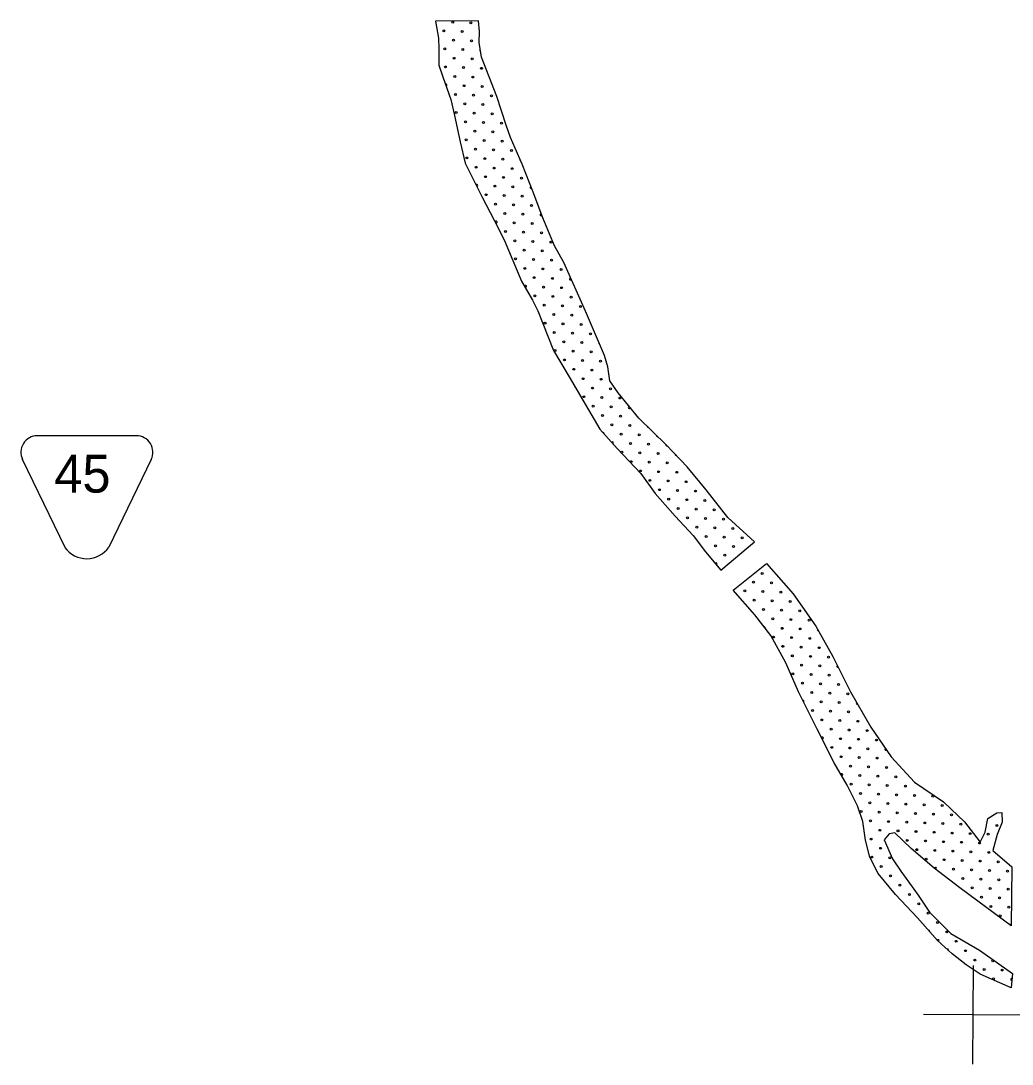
# Model space of a CAD drawing. Extents: x 1612280 to 1883141, y 560852 to 780851.
# Drawn here: x 1761295 to 1772365, y 697806 to 709453 of the extents above; entities that cross this region are included whole.
import ezdxf

# ---------------------------------------------------------------- set-up
doc = ezdxf.new("R2010")
doc.units = 0
for name, color, linetype in [('DESIGN - ROW - Easement Linework and Patterning', 7, 'Continuous'), ('DESIGN - SCRATCH - User 1', 7, 'Continuous'), ('DESIGN - TRAFFIC CONTROL PERMANENT - Pavement Marking Text', 7, 'Continuous'), ('SURVEY - DRAINAGE - Bridge Hydraulic Data - Points - Locators', 7, 'Continuous')]:
    doc.layers.add(name, color=color, linetype=linetype)

msp = doc.modelspace()

# ---------------------------------------------------------------- linework, layer by layer
at = {"layer": 'DESIGN - ROW - Easement Linework and Patterning'}
for p, q in [((1762584, 704821), (1761480, 704821)), ((1762584, 704821), (1761480, 704821)), ((1761788, 703575), (1761313, 704555)), ((1761788, 703575), (1761313, 704555)), ((1762750, 704555), (1762277, 703578)), ((1762750, 704555), (1762277, 703578))]:
    msp.add_line(p, q, dxfattribs=at)
for centre, radius, start, end in [((1761480, 704636), 185, 90.0012, 205.8236), ((1761480, 704636), 185, 90.0012, 205.8236), ((1762584, 704636), 185, 334.1799, 90.0012), ((1762584, 704636), 185, 334.1799, 90.0012), ((1762031, 703746), 298, 215.1371, 325.5451), ((1762031, 703746), 298, 215.1371, 325.5451)]:
    msp.add_arc(centre, radius, start, end, dxfattribs=at)
at = {"layer": 'DESIGN - SCRATCH - User 1'}
for points in [[(1767357, 706757), (1767255, 706943), (1767122, 707255), (1767014, 707541), (1766892, 707853), (1766764, 708149), (1766713, 708287), (1766611, 708609), (1766437, 709049), (1766412, 709213), (1766417, 709335), (1766406, 709453), (1765926, 709448), (1765957, 709259), (1765962, 709141), (1765962, 708957), (1766008, 708829), (1766095, 708574), (1766136, 708395), (1766202, 708103), (1766258, 707863), (1766340, 707699), (1766447, 707485), (1766580, 707229), (1766692, 707007)], [(1767357, 706757), (1767255, 706943), (1767122, 707255), (1767014, 707541), (1766892, 707853), (1766764, 708149), (1766713, 708287), (1766611, 708609), (1766437, 709049), (1766412, 709213), (1766417, 709335), (1766406, 709453), (1765926, 709448), (1765957, 709259), (1765962, 709141), (1765962, 708957), (1766008, 708829), (1766095, 708574), (1766136, 708395), (1766202, 708103), (1766258, 707863), (1766340, 707699), (1766447, 707485), (1766580, 707229), (1766692, 707007)], [(1766692, 707007), (1766885, 706546), (1767010, 706336), (1767067, 706217), (1767243, 705774), (1767419, 705478), (1767635, 705109), (1767760, 704893), (1767953, 704677), (1768220, 704399), (1768379, 704177), (1768600, 703922), (1768804, 703706), (1768941, 703524), (1769111, 703319)], [(1766692, 707007), (1766885, 706546), (1767010, 706336), (1767067, 706217), (1767243, 705774), (1767419, 705478), (1767635, 705109), (1767760, 704893), (1767953, 704677), (1768220, 704399), (1768379, 704177), (1768600, 703922), (1768804, 703706), (1768941, 703524), (1769111, 703319)], [(1769111, 703319), (1769486, 703638), (1769190, 703910), (1768946, 704217), (1768736, 704473), (1768503, 704717), (1768197, 705018), (1767964, 705302), (1767873, 705433), (1767850, 705592), (1767811, 705717), (1767601, 706211), (1767357, 706757)], [(1769111, 703319), (1769486, 703638), (1769190, 703910), (1768946, 704217), (1768736, 704473), (1768503, 704717), (1768197, 705018), (1767964, 705302), (1767873, 705433), (1767850, 705592), (1767811, 705717), (1767601, 706211), (1767357, 706757)], [(1769251, 703096), (1769621, 703396), (1769920, 703057), (1770172, 702694), (1770361, 702356), (1770558, 701962), (1770786, 701568), (1771015, 701237), (1771274, 700953), (1771597, 700733), (1771684, 700654), (1771833, 700512), (1772007, 700284)], [(1769251, 703096), (1769621, 703396), (1769920, 703057), (1770172, 702694), (1770361, 702356), (1770558, 701962), (1770786, 701568), (1771015, 701237), (1771274, 700953), (1771597, 700733), (1771684, 700654), (1771833, 700512), (1772007, 700284)], [(1770697, 700514), (1770638, 700689), (1770522, 700919), (1770378, 701168), (1770186, 701545), (1769979, 701963), (1769836, 702287), (1769670, 702592), (1769490, 702822), (1769251, 703096)], [(1770697, 700514), (1770638, 700689), (1770522, 700919), (1770378, 701168), (1770186, 701545), (1769979, 701963), (1769836, 702287), (1769670, 702592), (1769490, 702822), (1769251, 703096)], [(1772007, 700284), (1772064, 700397), (1772092, 700547), (1772195, 700611), (1772249, 700615), (1772252, 700508), (1772199, 700369), (1772149, 700191), (1772363, 700009), (1772352, 699350), (1771782, 699774), (1771494, 699995), (1771238, 700212), (1771056, 700387), (1770992, 700376)], [(1772007, 700284), (1772064, 700397), (1772092, 700547), (1772195, 700611), (1772249, 700615), (1772252, 700508), (1772199, 700369), (1772149, 700191), (1772363, 700009), (1772352, 699350), (1771782, 699774), (1771494, 699995), (1771238, 700212), (1771056, 700387), (1770992, 700376)], [(1770992, 700376), (1770934, 700309), (1771029, 700097), (1771122, 699959), (1771316, 699692), (1771443, 699502), (1771680, 699264), (1772001, 699079), (1772368, 698819), (1772353, 698657), (1772009, 698810), (1771850, 698914), (1771694, 699036), (1771530, 699186), (1771307, 699438), (1771061, 699698), (1770868, 699935), (1770775, 700115), (1770726, 700306), (1770697, 700514)], [(1770992, 700376), (1770934, 700309), (1771029, 700097), (1771122, 699959), (1771316, 699692), (1771443, 699502), (1771680, 699264), (1772001, 699079), (1772368, 698819), (1772353, 698657), (1772009, 698810), (1771850, 698914), (1771694, 699036), (1771530, 699186), (1771307, 699438), (1771061, 699698), (1770868, 699935), (1770775, 700115), (1770726, 700306), (1770697, 700514)]]:
    msp.add_lwpolyline(points, dxfattribs=at)
for centre in [(1767260, 705772), (1767260, 705772), (1767461, 705765), (1767461, 705765), (1767364, 705667), (1767364, 705667), (1767566, 705660), (1767566, 705660), (1770769, 700924), (1770769, 700924), (1770873, 700820), (1770873, 700820), (1770978, 700715), (1770978, 700715), (1771082, 700610), (1771082, 700610)]:
    msp.add_circle(centre, 10.6, dxfattribs=at)
at = {"layer": 'DESIGN - TRAFFIC CONTROL PERMANENT - Pavement Marking Text'}
for centre in [(1766117, 709438), (1766117, 709438), (1766319, 709431), (1766319, 709431), (1766020, 709341), (1766020, 709341), (1766222, 709334), (1766222, 709334), (1766125, 709237), (1766125, 709237), (1766326, 709229), (1766326, 709229), (1766028, 709140), (1766028, 709140), (1766229, 709132), (1766229, 709132), (1766132, 709035), (1766132, 709035), (1766334, 709028), (1766334, 709028), (1766035, 708938), (1766035, 708938), (1766237, 708931), (1766237, 708931), (1766438, 708923), (1766438, 708923), (1766140, 708833), (1766140, 708833), (1766244, 708729), (1766244, 708729), (1766341, 708826), (1766341, 708826), (1766147, 708632), (1766147, 708632), (1766349, 708624), (1766349, 708624), (1766446, 708721), (1766446, 708721), (1766550, 708617), (1766550, 708617), (1766252, 708527), (1766252, 708527), (1766453, 708520), (1766453, 708520), (1766155, 708430), (1766155, 708430), (1766356, 708423), (1766356, 708423), (1766558, 708415), (1766558, 708415), (1766259, 708326), (1766259, 708326), (1766461, 708318), (1766461, 708318), (1766662, 708311), (1766662, 708311), (1766364, 708221), (1766364, 708221), (1766565, 708214), (1766565, 708214), (1766267, 708124), (1766267, 708124), (1766468, 708117), (1766468, 708117), (1766670, 708109), (1766670, 708109), (1766274, 707922), (1766274, 707922), (1766371, 708020), (1766371, 708020), (1766476, 707915), (1766476, 707915), (1766573, 708012), (1766573, 708012), (1766774, 708005), (1766774, 708005), (1766379, 707818), (1766379, 707818), (1766580, 707810), (1766580, 707810), (1766677, 707908), (1766677, 707908), (1766782, 707803), (1766782, 707803), (1766483, 707713), (1766483, 707713), (1766685, 707706), (1766685, 707706), (1766886, 707698), (1766886, 707698), (1766588, 707609), (1766588, 707609), (1766789, 707601), (1766789, 707601), (1766491, 707512), (1766491, 707512), (1766692, 707504), (1766692, 707504), (1766894, 707497), (1766894, 707497), (1766595, 707407), (1766595, 707407), (1766797, 707400), (1766797, 707400), (1766998, 707392), (1766998, 707392), (1766700, 707303), (1766700, 707303), (1766901, 707295), (1766901, 707295), (1766707, 707101), (1766707, 707101), (1766804, 707198), (1766804, 707198), (1767006, 707191), (1767006, 707191), (1766812, 706997), (1766812, 706997), (1766909, 707094), (1766909, 707094), (1767013, 706989), (1767013, 706989), (1767110, 707086), (1767110, 707086), (1767215, 706982), (1767215, 706982), (1766916, 706892), (1766916, 706892), (1767118, 706885), (1767118, 706885), (1766819, 706795), (1766819, 706795), (1767021, 706788), (1767021, 706788), (1767222, 706780), (1767222, 706780), (1766924, 706690), (1766924, 706690), (1767125, 706683), (1767125, 706683), (1767327, 706676), (1767327, 706676), (1767028, 706586), (1767028, 706586), (1767230, 706578), (1767230, 706578), (1767133, 706481), (1767133, 706481), (1767334, 706474), (1767334, 706474), (1767036, 706384), (1767036, 706384), (1767237, 706377), (1767237, 706377), (1767439, 706369), (1767439, 706369), (1767140, 706280), (1767140, 706280), (1767245, 706175), (1767245, 706175), (1767342, 706272), (1767342, 706272), (1767446, 706168), (1767446, 706168), (1767543, 706265), (1767543, 706265), (1767148, 706078), (1767148, 706078), (1767349, 706071), (1767349, 706071), (1767551, 706063), (1767551, 706063), (1767252, 705974), (1767252, 705974), (1767454, 705966), (1767454, 705966), (1767655, 705959), (1767655, 705959), (1767357, 705869), (1767357, 705869), (1767558, 705862), (1767558, 705862), (1767663, 705757), (1767663, 705757), (1767767, 705653), (1767767, 705653), (1767469, 705563), (1767469, 705563), (1767670, 705555), (1767670, 705555), (1767573, 705458), (1767573, 705458), (1767678, 705354), (1767678, 705354), (1767775, 705451), (1767775, 705451), (1767581, 705257), (1767581, 705257), (1767782, 705249), (1767782, 705249), (1767879, 705346), (1767879, 705346), (1767984, 705242), (1767984, 705242), (1767685, 705152), (1767685, 705152), (1767887, 705145), (1767887, 705145), (1767790, 705048), (1767790, 705048), (1767991, 705040), (1767991, 705040), (1767894, 704943), (1767894, 704943), (1768096, 704936), (1768096, 704936), (1767999, 704839), (1767999, 704839), (1768201, 704831), (1768201, 704831), (1768103, 704734), (1768103, 704734), (1768305, 704727), (1768305, 704727), (1768006, 704637), (1768006, 704637), (1768208, 704630), (1768208, 704630), (1768410, 704622), (1768410, 704622), (1768111, 704532), (1768111, 704532), (1768215, 704428), (1768215, 704428), (1768313, 704525), (1768313, 704525), (1768417, 704420), (1768417, 704420), (1768514, 704518), (1768514, 704518), (1768320, 704323), (1768320, 704323), (1768522, 704316), (1768522, 704316), (1768619, 704413), (1768619, 704413), (1768723, 704308), (1768723, 704308), (1768425, 704219), (1768425, 704219), (1768626, 704211), (1768626, 704211), (1768828, 704204), (1768828, 704204), (1768529, 704114), (1768529, 704114), (1768731, 704107), (1768731, 704107), (1768932, 704099), (1768932, 704099), (1768634, 704010), (1768634, 704010), (1768835, 704002), (1768835, 704002), (1769037, 703995), (1769037, 703995), (1768738, 703905), (1768738, 703905), (1768940, 703898), (1768940, 703898), (1769141, 703890), (1769141, 703890), (1768843, 703801), (1768843, 703801), (1769044, 703793), (1769044, 703793), (1769246, 703786), (1769246, 703786), (1768947, 703696), (1768947, 703696), (1769149, 703689), (1769149, 703689), (1769350, 703681), (1769350, 703681), (1769052, 703592), (1769052, 703592), (1769156, 703487), (1769156, 703487), (1769253, 703584), (1769253, 703584), (1769574, 703284), (1769574, 703284), (1769477, 703187), (1769477, 703187), (1769678, 703179), (1769678, 703179), (1769380, 703090), (1769380, 703090), (1769581, 703082), (1769581, 703082), (1769783, 703075), (1769783, 703075), (1769484, 702985), (1769484, 702985), (1769686, 702978), (1769686, 702978), (1769887, 702970), (1769887, 702970), (1769589, 702880), (1769589, 702880), (1769790, 702873), (1769790, 702873), (1769992, 702866), (1769992, 702866), (1769693, 702776), (1769693, 702776), (1769798, 702671), (1769798, 702671), (1769895, 702768), (1769895, 702768), (1770097, 702761), (1770097, 702761), (1769701, 702574), (1769701, 702574), (1769902, 702567), (1769902, 702567), (1769999, 702664), (1769999, 702664), (1770104, 702559), (1770104, 702559), (1769805, 702470), (1769805, 702470), (1770007, 702462), (1770007, 702462), (1770209, 702455), (1770209, 702455), (1769910, 702365), (1769910, 702365), (1770112, 702358), (1770112, 702358), (1770313, 702350), (1770313, 702350), (1770014, 702261), (1770014, 702261), (1770216, 702253), (1770216, 702253), (1769917, 702164), (1769917, 702164), (1770119, 702156), (1770119, 702156), (1770321, 702149), (1770321, 702149), (1770022, 702059), (1770022, 702059), (1770224, 702052), (1770224, 702052), (1770425, 702044), (1770425, 702044), (1770126, 701955), (1770126, 701955), (1770328, 701947), (1770328, 701947), (1770530, 701940), (1770530, 701940), (1770134, 701753), (1770134, 701753), (1770231, 701850), (1770231, 701850), (1770336, 701745), (1770336, 701745), (1770433, 701843), (1770433, 701843), (1770537, 701738), (1770537, 701738), (1770238, 701648), (1770238, 701648), (1770440, 701641), (1770440, 701641), (1770642, 701633), (1770642, 701633), (1770343, 701544), (1770343, 701544), (1770545, 701536), (1770545, 701536), (1770746, 701529), (1770746, 701529), (1770448, 701439), (1770448, 701439), (1770649, 701432), (1770649, 701432), (1770851, 701424), (1770851, 701424), (1770350, 701342), (1770350, 701342), (1770552, 701335), (1770552, 701335), (1770754, 701327), (1770754, 701327), (1770455, 701238), (1770455, 701238), (1770657, 701230), (1770657, 701230), (1770858, 701223), (1770858, 701223), (1770560, 701133), (1770560, 701133), (1770761, 701126), (1770761, 701126), (1770963, 701118), (1770963, 701118), (1770567, 700932), (1770567, 700932), (1770664, 701029), (1770664, 701029), (1770866, 701021), (1770866, 701021), (1771067, 701014), (1771067, 701014), (1770672, 700827), (1770672, 700827), (1770970, 700917), (1770970, 700917), (1771075, 700812), (1771075, 700812), (1771172, 700909), (1771172, 700909), (1770776, 700722), (1770776, 700722), (1771179, 700708), (1771179, 700708), (1771276, 700805), (1771276, 700805), (1771381, 700700), (1771381, 700700), (1771478, 700797), (1771478, 700797), (1771583, 700693), (1771583, 700693), (1770679, 700625), (1770679, 700625), (1770881, 700618), (1770881, 700618), (1771284, 700603), (1771284, 700603), (1771485, 700596), (1771485, 700596), (1771687, 700588), (1771687, 700588), (1770784, 700521), (1770784, 700521), (1770985, 700513), (1770985, 700513), (1771187, 700506), (1771187, 700506), (1771388, 700498), (1771388, 700498), (1771590, 700491), (1771590, 700491), (1771792, 700484), (1771792, 700484), (1772195, 700469), (1772195, 700469), (1770888, 700416), (1770888, 700416), (1771090, 700409), (1771090, 700409), (1771291, 700401), (1771291, 700401), (1771493, 700394), (1771493, 700394), (1771695, 700386), (1771695, 700386), (1771896, 700379), (1771896, 700379), (1772098, 700372), (1772098, 700372), (1770791, 700319), (1770791, 700319), (1771194, 700304), (1771194, 700304), (1771396, 700297), (1771396, 700297), (1771597, 700289), (1771597, 700289), (1771799, 700282), (1771799, 700282), (1772001, 700274), (1772001, 700274), (1770798, 700118), (1770798, 700118), (1770896, 700215), (1770896, 700215), (1771000, 700110), (1771000, 700110), (1771299, 700200), (1771299, 700200), (1771500, 700192), (1771500, 700192), (1771702, 700185), (1771702, 700185), (1771904, 700177), (1771904, 700177), (1772105, 700170), (1772105, 700170), (1770903, 700013), (1770903, 700013), (1771403, 700095), (1771403, 700095), (1771605, 700088), (1771605, 700088), (1771807, 700080), (1771807, 700080), (1772008, 700073), (1772008, 700073), (1772210, 700065), (1772210, 700065), (1771008, 699909), (1771008, 699909), (1771709, 699983), (1771709, 699983), (1771814, 699879), (1771814, 699879), (1771911, 699976), (1771911, 699976), (1772113, 699968), (1772113, 699968), (1772314, 699961), (1772314, 699961), (1771112, 699804), (1771112, 699804), (1771919, 699774), (1771919, 699774), (1772016, 699871), (1772016, 699871), (1772120, 699767), (1772120, 699767), (1772217, 699864), (1772217, 699864), (1772322, 699759), (1772322, 699759), (1771217, 699700), (1771217, 699700), (1772023, 699670), (1772023, 699670), (1772225, 699662), (1772225, 699662), (1771321, 699595), (1771321, 699595), (1772128, 699565), (1772128, 699565), (1772329, 699558), (1772329, 699558), (1771426, 699490), (1771426, 699490), (1772232, 699461), (1772232, 699461), (1771530, 699386), (1771530, 699386), (1771635, 699281), (1771635, 699281), (1771739, 699177), (1771739, 699177), (1771844, 699072), (1771844, 699072), (1771948, 698968), (1771948, 698968), (1772150, 698960), (1772150, 698960), (1772053, 698863), (1772053, 698863), (1772255, 698856), (1772255, 698856), (1772157, 698759), (1772157, 698759)]:
    msp.add_circle(centre, 10.6, dxfattribs=at)
for centre, start, end in [((1766423, 709326), 129.6097, 225.6227), ((1766431, 709125), 130.1007, 247.6519), ((1766043, 708736), 272.7009, 124.8327), ((1766879, 707900), 153.6632, 252.9455), ((1766386, 707616), 273.9673, 139.1355), ((1766991, 707594), 97.7025, 305.2243), ((1767103, 707288), 75.9264, 325.1629), ((1766603, 707206), 232.4215, 181.0593), ((1767431, 706571), 69.0837, 339.1456), ((1766931, 706489), 229.0425, 192.3955), ((1767760, 705854), 154.2599, 251.7921), ((1767476, 705361), 5.4531, 55.1371), ((1768089, 705137), 78.3763, 0.2895), ((1768193, 705033), 166.6196, 272.0463), ((1768298, 704928), 173.5478, 277.4866), ((1767797, 704846), 329.7829, 113.82), ((1768402, 704824), 164.8382, 286.1962), ((1767902, 704742), 283.6091, 159.9939), ((1768507, 704719), 156.8216, 292.1704), ((1768611, 704615), 178.3163, 268.9191), ((1768955, 703495), 358.6094, 80.9645), ((1769059, 703390), 278.4975, 161.0764), ((1769596, 702679), 336.0264, 100.3365), ((1770201, 702656), 159.1209, 259.1829), ((1770418, 702246), 124.4729, 288.627), ((1770029, 701857), 307.3499, 105.3369), ((1770634, 701835), 133.5084, 286.6876), ((1770246, 701447), 243.6505, 170.3639), ((1770955, 701320), 115.1389, 314.0752), ((1770462, 701036), 258.445, 161.3851), ((1771508, 699991), 292.4126, 172.6875), ((1772337, 699356), 346.6842, 120.001), ((1771433, 699289), 335.3391, 107.6475), ((1771538, 699184), 295.2699, 158.3678), ((1771642, 699080), 332.5065, 122.7106), ((1772359, 698751), 69.9515, 279.8478)]:
    msp.add_arc(centre, 10.6, start, end, dxfattribs=at)
at = {"layer": 'SURVEY - DRAINAGE - Bridge Hydraulic Data - Points - Locators'}
for p, q in [((1771930, 698906), (1771922, 697806)), ((1771930, 698906), (1771922, 697806)), ((1772476, 698352), (1771376, 698360)), ((1772476, 698352), (1771376, 698360))]:
    msp.add_line(p, q, dxfattribs=at)

# ---------------------------------------------------------------- texts
at = {"layer": 'DESIGN - ROW - Easement Linework and Patterning'}
msp.add_text('45', height=422.4, rotation=0.0012, dxfattribs=at).set_placement((1761668, 704186))
msp.add_text('45', height=422.4, rotation=0.0012, dxfattribs=at).set_placement((1761668, 704186))

doc.saveas('drawing.dxf')
